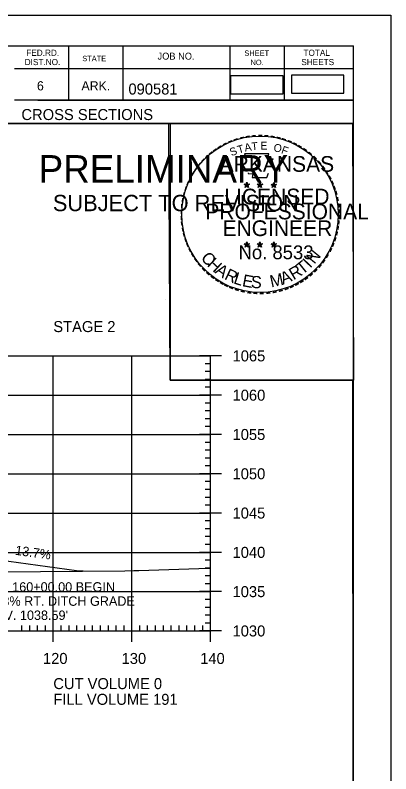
# Model space of a CAD drawing. Extents: x 1322838 to 1324533, y 339903 to 351025.
# Drawn here: x 1323818.9 to 1323866.6, y 345655.6 to 345752.1 of the extents above; entities that cross this region are included whole.
import ezdxf

# ---------------------------------------------------------------- set-up
doc = ezdxf.new("R2010")
doc.units = 0
for name, color, linetype in [('R_Axis', 7, 'Continuous'), ('R_Axis Annot', 7, 'Continuous'), ('R_Border', 7, 'Continuous'), ('R_Border PE', 7, 'Continuous'), ('R_Border Prem', 7, 'Continuous'), ('R_Drive', 7, 'Continuous'), ('R_Exist Surface', 7, 'Continuous'), ('R_Grid', 7, 'Continuous'), ('R_No Plot', 7, 'Continuous')]:
    doc.layers.add(name, color=color, linetype=linetype)

msp = doc.modelspace()

# ---------------------------------------------------------------- linework, layer by layer
at = {"layer": 'R_Axis'}
for p, q in [((1323845.115, 345708.745), (1323842.315, 345708.745)), ((1323843.715, 345673.745), (1323843.715, 345708.745)), ((1323843.715, 345707.745), (1323843.015, 345707.745)), ((1323843.715, 345706.745), (1323843.015, 345706.745)), ((1323843.715, 345705.745), (1323843.015, 345705.745)), ((1323843.715, 345704.745), (1323843.015, 345704.745)), ((1323845.115, 345703.745), (1323842.315, 345703.745)), ((1323843.715, 345702.745), (1323843.015, 345702.745)), ((1323843.715, 345701.745), (1323843.015, 345701.745)), ((1323843.715, 345700.745), (1323843.015, 345700.745)), ((1323843.715, 345699.745), (1323843.015, 345699.745)), ((1323845.115, 345698.745), (1323842.315, 345698.745)), ((1323843.715, 345697.745), (1323843.015, 345697.745)), ((1323843.715, 345696.745), (1323843.015, 345696.745)), ((1323843.715, 345695.745), (1323843.015, 345695.745)), ((1323843.715, 345694.745), (1323843.015, 345694.745)), ((1323845.115, 345693.745), (1323842.315, 345693.745)), ((1323843.715, 345692.745), (1323843.015, 345692.745)), ((1323843.715, 345691.745), (1323843.015, 345691.745)), ((1323843.715, 345690.745), (1323843.015, 345690.745)), ((1323843.715, 345689.745), (1323843.015, 345689.745)), ((1323845.115, 345688.745), (1323842.315, 345688.745)), ((1323843.715, 345687.745), (1323843.015, 345687.745)), ((1323843.715, 345686.745), (1323843.015, 345686.745)), ((1323843.715, 345685.745), (1323843.015, 345685.745)), ((1323843.715, 345684.745), (1323843.015, 345684.745)), ((1323845.115, 345683.745), (1323842.315, 345683.745)), ((1323843.715, 345682.745), (1323843.015, 345682.745)), ((1323843.715, 345681.745), (1323843.015, 345681.745)), ((1323843.715, 345680.745), (1323843.015, 345680.745)), ((1323843.715, 345679.745), (1323843.015, 345679.745)), ((1323845.115, 345678.745), (1323842.315, 345678.745)), ((1323843.715, 345677.745), (1323843.015, 345677.745)), ((1323843.715, 345676.745), (1323843.015, 345676.745)), ((1323843.715, 345675.745), (1323843.015, 345675.745)), ((1323819.715, 345673.745), (1323819.715, 345674.445)), ((1323820.715, 345673.745), (1323820.715, 345674.445)), ((1323821.715, 345673.745), (1323821.715, 345674.445)), ((1323822.715, 345673.745), (1323822.715, 345674.445)), ((1323823.715, 345672.345), (1323823.715, 345675.145)), ((1323824.715, 345673.745), (1323824.715, 345674.445)), ((1323825.715, 345673.745), (1323825.715, 345674.445)), ((1323826.715, 345673.745), (1323826.715, 345674.445)), ((1323827.715, 345673.745), (1323827.715, 345674.445)), ((1323828.715, 345673.745), (1323828.715, 345674.445)), ((1323829.715, 345673.745), (1323829.715, 345674.445)), ((1323830.715, 345673.745), (1323830.715, 345674.445)), ((1323831.715, 345673.745), (1323831.715, 345674.445)), ((1323832.715, 345673.745), (1323832.715, 345674.445)), ((1323833.715, 345672.345), (1323833.715, 345675.145)), ((1323834.715, 345673.745), (1323834.715, 345674.445)), ((1323835.715, 345673.745), (1323835.715, 345674.445)), ((1323836.715, 345673.745), (1323836.715, 345674.445)), ((1323837.715, 345673.745), (1323837.715, 345674.445)), ((1323838.715, 345673.745), (1323838.715, 345674.445)), ((1323839.715, 345673.745), (1323839.715, 345674.445)), ((1323840.715, 345673.745), (1323840.715, 345674.445)), ((1323841.715, 345673.745), (1323841.715, 345674.445)), ((1323842.715, 345673.745), (1323842.715, 345674.445)), ((1323843.715, 345674.745), (1323843.015, 345674.745)), ((1323843.715, 345672.345), (1323843.715, 345675.145)), ((1323563.715, 345673.745), (1323843.715, 345673.745)), ((1323845.115, 345673.745), (1323842.315, 345673.745))]:
    msp.add_line(p, q, dxfattribs=at)
at = {"layer": 'R_Border'}
for p, q in [((1323545.715, 345748.205), (1323861.895, 345748.205)), ((1323825.635, 345748.205), (1323825.635, 345741.265)), ((1323832.575, 345748.205), (1323832.575, 345741.265)), ((1323846.155, 345748.205), (1323846.155, 345741.265)), ((1323853.095, 345748.205), (1323853.095, 345741.265)), ((1323861.895, 345542.745), (1323861.895, 345748.205)), ((1323861.895, 345745.265), (1323818.795, 345745.265)), ((1323861.895, 345745.285), (1323861.895, 345745.285)), ((1323861.895, 345741.265), (1323818.795, 345741.265)), ((1323821.755, 345741.265), (1323861.895, 345741.265)), ((1323861.895, 345738.325), (1323799.255, 345738.325))]:
    msp.add_line(p, q, dxfattribs=at)
at = {"layer": 'R_Border PE'}
for p, q in [((1323847.98, 345730.58), (1323848.329, 345730.469)), ((1323847.98, 345730.58), (1323848.233, 345730.535)), ((1323847.98, 345730.58), (1323848.217, 345730.458)), ((1323848.113, 345730.172), (1323848.329, 345730.469)), ((1323848.113, 345730.172), (1323848.239, 345730.416)), ((1323848.329, 345730.834), (1323848.288, 345730.582)), ((1323848.329, 345730.469), (1323848.329, 345730.834)), ((1323848.329, 345730.834), (1323848.378, 345730.584)), ((1323848.676, 345730.58), (1323848.329, 345730.469)), ((1323848.542, 345730.172), (1323848.329, 345730.469)), ((1323848.676, 345730.58), (1323848.39, 345730.531)), ((1323848.542, 345730.172), (1323848.405, 345730.463)), ((1323848.676, 345730.58), (1323848.472, 345730.478)), ((1323849.65, 345730.58), (1323849.999, 345730.469)), ((1323849.65, 345730.58), (1323849.903, 345730.535)), ((1323849.65, 345730.58), (1323849.887, 345730.458)), ((1323849.783, 345730.172), (1323849.999, 345730.469)), ((1323849.783, 345730.172), (1323849.909, 345730.416)), ((1323849.999, 345730.834), (1323849.958, 345730.582)), ((1323849.999, 345730.469), (1323849.999, 345730.834)), ((1323849.999, 345730.834), (1323850.048, 345730.584)), ((1323850.346, 345730.58), (1323849.999, 345730.469)), ((1323850.212, 345730.172), (1323849.999, 345730.469)), ((1323850.346, 345730.58), (1323850.06, 345730.531)), ((1323850.212, 345730.172), (1323850.075, 345730.463)), ((1323850.346, 345730.58), (1323850.142, 345730.478)), ((1323851.414, 345730.568), (1323851.763, 345730.457)), ((1323851.414, 345730.568), (1323851.667, 345730.523)), ((1323851.414, 345730.568), (1323851.651, 345730.446)), ((1323851.547, 345730.16), (1323851.763, 345730.457)), ((1323851.547, 345730.16), (1323851.673, 345730.404)), ((1323851.763, 345730.822), (1323851.722, 345730.57)), ((1323851.763, 345730.457), (1323851.763, 345730.822)), ((1323851.763, 345730.822), (1323851.812, 345730.572)), ((1323852.11, 345730.568), (1323851.763, 345730.457)), ((1323851.976, 345730.16), (1323851.763, 345730.457)), ((1323852.11, 345730.568), (1323851.824, 345730.519)), ((1323851.976, 345730.16), (1323851.839, 345730.451)), ((1323852.11, 345730.568), (1323851.906, 345730.466)), ((1323848.113, 345730.172), (1323848.327, 345730.389)), ((1323848.542, 345730.172), (1323848.327, 345730.386)), ((1323849.783, 345730.172), (1323849.997, 345730.389)), ((1323850.212, 345730.172), (1323849.997, 345730.386)), ((1323851.547, 345730.16), (1323851.761, 345730.377)), ((1323851.976, 345730.16), (1323851.761, 345730.374)), ((1323847.976, 345723.007), (1323848.325, 345722.896)), ((1323847.976, 345723.007), (1323848.229, 345722.962)), ((1323847.976, 345723.007), (1323848.213, 345722.885)), ((1323848.109, 345722.599), (1323848.325, 345722.896)), ((1323848.109, 345722.599), (1323848.235, 345722.843)), ((1323848.109, 345722.599), (1323848.323, 345722.816)), ((1323848.325, 345723.261), (1323848.284, 345723.009)), ((1323848.538, 345722.599), (1323848.323, 345722.813)), ((1323848.325, 345722.896), (1323848.325, 345723.261)), ((1323848.325, 345723.261), (1323848.374, 345723.011)), ((1323848.672, 345723.007), (1323848.325, 345722.896)), ((1323848.538, 345722.599), (1323848.325, 345722.896)), ((1323848.672, 345723.007), (1323848.386, 345722.958)), ((1323848.538, 345722.599), (1323848.401, 345722.89)), ((1323848.672, 345723.007), (1323848.468, 345722.905)), ((1323849.645, 345723.007), (1323849.994, 345722.896)), ((1323849.645, 345723.007), (1323849.898, 345722.962)), ((1323849.645, 345723.007), (1323849.882, 345722.885)), ((1323849.778, 345722.599), (1323849.994, 345722.896)), ((1323849.778, 345722.599), (1323849.904, 345722.843)), ((1323849.778, 345722.599), (1323849.992, 345722.816)), ((1323849.994, 345723.261), (1323849.953, 345723.009)), ((1323850.207, 345722.599), (1323849.992, 345722.813)), ((1323849.994, 345722.896), (1323849.994, 345723.261)), ((1323849.994, 345723.261), (1323850.043, 345723.011)), ((1323850.341, 345723.007), (1323849.994, 345722.896)), ((1323850.207, 345722.599), (1323849.994, 345722.896)), ((1323850.341, 345723.007), (1323850.055, 345722.958)), ((1323850.207, 345722.599), (1323850.07, 345722.89)), ((1323850.341, 345723.007), (1323850.137, 345722.905)), ((1323851.412, 345722.997), (1323851.761, 345722.886)), ((1323851.412, 345722.997), (1323851.665, 345722.952)), ((1323851.412, 345722.997), (1323851.649, 345722.875)), ((1323851.545, 345722.589), (1323851.761, 345722.886)), ((1323851.545, 345722.589), (1323851.671, 345722.833)), ((1323851.545, 345722.589), (1323851.759, 345722.806)), ((1323851.761, 345723.251), (1323851.72, 345722.999)), ((1323851.974, 345722.589), (1323851.759, 345722.803)), ((1323851.761, 345722.886), (1323851.761, 345723.251)), ((1323851.761, 345723.251), (1323851.81, 345723.001)), ((1323852.108, 345722.997), (1323851.761, 345722.886)), ((1323851.974, 345722.589), (1323851.761, 345722.886)), ((1323852.108, 345722.997), (1323851.822, 345722.948)), ((1323851.974, 345722.589), (1323851.837, 345722.88)), ((1323852.108, 345722.997), (1323851.904, 345722.895))]:
    msp.add_line(p, q, dxfattribs=at)
for points in [[(1323848.021, 345734.458), (1323848.29, 345733.631)], [(1323851.532, 345733.536), (1323851.674, 345733.82), (1323850.989, 345733.796), (1323851.137, 345734.458), (1323848.021, 345734.458)], [(1323848.513, 345732.035), (1323848.513, 345731.948), (1323849.076, 345731.929), (1323849.022, 345731.456), (1323850.892, 345731.456), (1323851.093, 345731.992)], [(1323848.329, 345730.834), (1323848.542, 345730.172), (1323847.98, 345730.58), (1323848.676, 345730.58), (1323848.113, 345730.172), (1323848.329, 345730.834)], [(1323849.999, 345730.834), (1323850.212, 345730.172), (1323849.65, 345730.58), (1323850.346, 345730.58), (1323849.783, 345730.172), (1323849.999, 345730.834)], [(1323851.763, 345730.822), (1323851.976, 345730.16), (1323851.414, 345730.568), (1323852.11, 345730.568), (1323851.547, 345730.16), (1323851.763, 345730.822)], [(1323848.325, 345723.261), (1323848.538, 345722.599), (1323847.976, 345723.007), (1323848.672, 345723.007), (1323848.109, 345722.599), (1323848.325, 345723.261)], [(1323849.994, 345723.261), (1323850.207, 345722.599), (1323849.645, 345723.007), (1323850.341, 345723.007), (1323849.778, 345722.599), (1323849.994, 345723.261)], [(1323851.761, 345723.251), (1323851.974, 345722.589), (1323851.412, 345722.997), (1323852.108, 345722.997), (1323851.545, 345722.589), (1323851.761, 345723.251)]]:
    msp.add_lwpolyline(points, dxfattribs=at)
for centre, radius in [((1323848.328, 345730.468), 0.172), ((1323848.328, 345730.468), 0.145), ((1323848.328, 345730.468), 0.116), ((1323848.328, 345730.468), 0.0991), ((1323848.328, 345730.468), 0.0747), ((1323848.328, 345730.468), 0.0495), ((1323848.328, 345730.468), 0.0296), ((1323849.998, 345730.468), 0.172), ((1323849.998, 345730.468), 0.145), ((1323849.998, 345730.468), 0.116), ((1323849.998, 345730.468), 0.0991), ((1323849.998, 345730.468), 0.0747), ((1323849.998, 345730.468), 0.0495), ((1323849.998, 345730.468), 0.0296), ((1323851.762, 345730.456), 0.172), ((1323851.762, 345730.456), 0.145), ((1323851.762, 345730.456), 0.116), ((1323851.762, 345730.456), 0.0991), ((1323851.762, 345730.456), 0.0747), ((1323851.762, 345730.456), 0.0495), ((1323851.762, 345730.456), 0.0296), ((1323848.324, 345722.895), 0.172), ((1323848.324, 345722.895), 0.145), ((1323848.324, 345722.895), 0.116), ((1323848.324, 345722.895), 0.0991), ((1323848.324, 345722.895), 0.0747), ((1323848.324, 345722.895), 0.0495), ((1323848.324, 345722.895), 0.0296), ((1323849.993, 345722.895), 0.172), ((1323849.993, 345722.895), 0.145), ((1323849.993, 345722.895), 0.116), ((1323849.993, 345722.895), 0.0991), ((1323849.993, 345722.895), 0.0747), ((1323849.993, 345722.895), 0.0495), ((1323849.993, 345722.895), 0.0296), ((1323851.76, 345722.885), 0.172), ((1323851.76, 345722.885), 0.145), ((1323851.76, 345722.885), 0.116), ((1323851.76, 345722.885), 0.0991), ((1323851.76, 345722.885), 0.0747), ((1323851.76, 345722.885), 0.0495), ((1323851.76, 345722.885), 0.0296)]:
    msp.add_circle(centre, radius, dxfattribs=at)
at = {"layer": 'R_Drive'}
for points in [[(1323846.253, 345742.086), (1323852.936, 345742.086), (1323852.936, 345744.396), (1323846.253, 345744.396)], [(1323853.999, 345742.169), (1323860.682, 345742.169), (1323860.682, 345744.479), (1323853.999, 345744.479)]]:
    msp.add_lwpolyline(points, close=True, dxfattribs=at)
msp.add_lwpolyline([(1323816.765, 345682.812), (1323826.672, 345681.452), (1323827.51, 345681.376)], dxfattribs=at)
at = {"layer": 'R_Exist Surface'}
msp.add_lwpolyline([(1323756.655, 345682.54), (1323773.488, 345682.087), (1323778.68, 345681.951), (1323778.94, 345681.946), (1323797.876, 345681.308), (1323800.585, 345681.201), (1323801.066, 345680.706), (1323803.42, 345679.339), (1323806.691, 345679.435), (1323808.978, 345679.487), (1323810.939, 345680.269), (1323814.282, 345681.112), (1323816.671, 345681.266), (1323832.816, 345681.397), (1323833.957, 345681.419), (1323834.587, 345681.449), (1323843.511, 345681.724), (1323843.715, 345681.73)], dxfattribs=at)
at = {"layer": 'R_Grid'}
for p, q in [((1323563.715, 345708.745), (1323843.715, 345708.745)), ((1323823.715, 345673.745), (1323823.715, 345708.745)), ((1323833.715, 345673.745), (1323833.715, 345708.745)), ((1323843.715, 345673.745), (1323843.715, 345708.745)), ((1323563.715, 345703.745), (1323843.715, 345703.745)), ((1323563.715, 345698.745), (1323843.715, 345698.745)), ((1323563.715, 345693.745), (1323843.715, 345693.745)), ((1323563.715, 345688.745), (1323843.715, 345688.745)), ((1323563.715, 345683.745), (1323843.715, 345683.745)), ((1323563.715, 345678.745), (1323843.715, 345678.745)), ((1323563.715, 345673.745), (1323843.715, 345673.745))]:
    msp.add_line(p, q, dxfattribs=at)
at = {"layer": 'R_No Plot'}
for p, q in [((1323533.315, 345752.099), (1323866.648, 345752.099)), ((1323837.93, 345715.869), (1323837.93, 345715.869))]:
    msp.add_line(p, q, dxfattribs=at)
for points in [[(1323533.308, 345752.099), (1323866.648, 345752.099), (1323866.648, 345538.762), (1323533.308, 345538.762)], [(1323779.635, 345748.205), (1323799.255, 345748.205), (1323799.255, 345738.325), (1323815.368, 345738.325), (1323838.567, 345738.325), (1323838.567, 345705.654), (1323861.775, 345705.654), (1323861.895, 345542.745), (1323545.715, 345542.745), (1323545.715, 345748.205)], [(1323838.427, 345738.325), (1323861.775, 345738.325), (1323861.915, 345705.654), (1323838.567, 345705.654)]]:
    msp.add_lwpolyline(points, close=True, dxfattribs=at)
msp.add_circle((1323850.007, 345726.765), 9.952, dxfattribs=at)

# ---------------------------------------------------------------- texts
at = {"layer": 'R_Axis Annot'}
for s, p in [('STAGE 2', (1323823.715, 345711.775)), ('1065', (1323846.515, 345708.045)), ('1060', (1323846.515, 345703.045)), ('1055', (1323846.515, 345698.045)), ('1050', (1323846.515, 345693.045)), ('1045', (1323846.515, 345688.045)), ('1040', (1323846.515, 345683.045)), ('1035', (1323846.515, 345678.045)), ('1030', (1323846.515, 345673.045)), ('120', (1323822.398, 345669.545)), ('130', (1323832.398, 345669.545)), ('140', (1323842.398, 345669.545)), ('CUT VOLUME 0', (1323823.715, 345666.345)), ('FILL VOLUME 191', (1323823.715, 345664.345))]:
    msp.add_text(s, height=1.4, dxfattribs=at).set_placement(p)
at = {"layer": 'R_Border'}
for s, height, p in [('FED.RD.', 0.7819, (1323820.275, 345746.925)), ('STATE', 0.684, (1323827.395, 345746.245)), ('JOB NO.', 0.8792, (1323836.975, 345746.445)), ('SHEET', 0.684, (1323848.015, 345746.925)), ('TOTAL', 0.7819, (1323855.535, 345746.925)), ('DIST.NO.', 0.7819, (1323820.075, 345745.745)), ('NO.', 0.684, (1323848.795, 345745.745)), ('SHEETS', 0.7819, (1323855.255, 345745.745)), ('6', 1.172, (1323821.635, 345742.525)), ('ARK.', 1.1723, (1323827.295, 345742.525)), ('090581', 1.4, (1323833.271, 345742.004)), ('CROSS SECTIONS', 1.4, (1323819.659, 345738.755))]:
    msp.add_text(s, height=height, rotation=360, dxfattribs=at).set_placement(p)
at = {"layer": 'R_Border PE'}
for s, height, rotation, p in [('-', 1.6, 24.30721, (1323846.135, 345735.316)), ('-', 1.6, 19.17608, (1323846.769, 345735.585)), ('-', 1.6, 13.63015, (1323847.519, 345735.826)), ('-', 1.6, 10.21935, (1323848.197, 345735.988)), ('-', 1.6, 5.89682, (1323848.926, 345736.098)), ('-', 1.6, 0.18623, (1323849.698, 345736.17)), ('-', 1.6, 357.74304, (1323850.421, 345736.157)), ('-', 1.6, 352.16172, (1323851.165, 345736.101)), ('-', 1.6, 347.20489, (1323851.884, 345735.987)), ('-', 1.6, 342.3362, (1323852.519, 345735.832)), ('-', 1.6, 337.85509, (1323853.254, 345735.609)), ('-', 1.6, 34.06357, (1323844.905, 345734.629)), ('-', 1.6, 28.79182, (1323845.502, 345734.999)), ('S', 1, 21.59401, (1323846.376, 345734.136)), ('T', 1, 16.4036, (1323847.29, 345734.467)), ('A', 1, 11.21318, (1323848.116, 345734.718)), ('T', 1, 6.02276, (1323848.965, 345734.884)), ('E', 1, 0.83234, (1323850.07, 345734.994)), ('O', 1, 350.4515, (1323851.674, 345734.784)), ('F', 1, 340.07066, (1323852.628, 345734.556)), ('-', 1.6, 334.12109, (1323853.885, 345735.338)), ('-', 1.6, 329.64089, (1323854.464, 345735.055)), ('-', 1.6, 42.96224, (1323843.418, 345733.439)), ('-', 1.6, 38.95066, (1323843.851, 345733.856)), ('-', 1.6, 36.23174, (1323844.327, 345734.234)), ('-', 1.6, 325.86266, (1323855.107, 345734.694)), ('-', 1.6, 320.52971, (1323855.717, 345734.268)), ('-', 1.6, 50.61417, (1323842.567, 345732.475)), ('-', 1.6, 48.42305, (1323842.97, 345732.961)), ('ARKANSAS', 2, 360, (1323844.874, 345732.17)), ('-', 1.6, 315.57859, (1323856.316, 345733.78)), ('-', 1.6, 309.87973, (1323856.885, 345733.23)), ('-', 1.6, 54.23247, (1323842.154, 345731.908)), ('-', 1.6, 306.65218, (1323857.41, 345732.628)), ('-', 1.4, 303.67529, (1323857.896, 345732.06)), ('-', 1.6, 62.87135, (1323841.516, 345730.767)), ('-', 1.6, 58.07063, (1323841.829, 345731.381)), ('-', 1.6, 299.66835, (1323858.215, 345731.453)), ('-', 1.6, 67.77427, (1323841.257, 345730.156)), ('DWB', 0.01, 360, (1323848.316, 345730.464)), ('DWB', 0.01, 360, (1323849.986, 345730.464)), ('DWB', 0.01, 360, (1323851.75, 345730.453)), ('-', 1.6, 294.66279, (1323858.539, 345730.841)), ('-', 1.6, 290.57283, (1323858.796, 345730.264)), ('-', 1.6, 75.46096, (1323840.841, 345728.812)), ('-', 1.6, 72.39447, (1323841.038, 345729.526)), ('LICENSED', 2, 360, (1323845.472, 345728.021)), ('-', 1.6, 285.12326, (1323859.03, 345729.684)), ('-', 1.6, 81.20126, (1323840.709, 345728.099)), ('-', 1.6, 280.54934, (1323859.23, 345728.942)), ('-', 1.6, 85.18634, (1323840.633, 345727.408)), ('PROFESSIONAL', 2, 360, (1323843.048, 345726.117)), ('-', 1.6, 276.59616, (1323859.392, 345728.174)), ('-', 1.6, 94.19588, (1323840.643, 345725.982)), ('-', 1.6, 89.06224, (1323840.608, 345726.707)), ('-', 1.6, 274.33011, (1323859.452, 345727.452)), ('-', 1.6, 269.94067, (1323859.486, 345726.82)), ('-', 1.6, 98.94793, (1323840.715, 345725.315)), ('ENGINEER', 2, 360, (1323845.235, 345723.992)), ('-', 1.6, 263.5172, (1323859.467, 345726.154)), ('-', 1.6, 101.71495, (1323840.85, 345724.582)), ('-', 1.6, 260.99529, (1323859.396, 345725.5)), ('-', 1.6, 105.45785, (1323841.012, 345723.987)), ('-', 1.6, 109.08742, (1323841.227, 345723.356)), ('-', 1.6, 252.86809, (1323859.105, 345724.102)), ('-', 1.6, 255.7626, (1323859.286, 345724.822)), ('-', 1.6, 114.06432, (1323841.481, 345722.76)), ('No. 8533', 1.757, 360, (1323847.278, 345721.041)), ('DWB', 0.01, 360, (1323848.312, 345722.891)), ('DWB', 0.01, 360, (1323849.981, 345722.891)), ('DWB', 0.01, 360, (1323851.748, 345722.881)), ('-', 1.6, 247.88866, (1323858.882, 345723.429)), ('-', 1.6, 115.72885, (1323841.786, 345722.142)), ('-', 1.6, 120.44712, (1323842.143, 345721.556)), ('C', 1.54, 309.95483, (1323842.4, 345721.188)), ('N', 1.54, 50.78344, (1323856.914, 345720.34)), ('-', 1.6, 244.61971, (1323858.62, 345722.8)), ('-', 1.6, 125.89344, (1323842.546, 345720.995)), ('H', 1.54, 317.38726, (1323843.185, 345720.25)), ('T', 1.54, 38.42805, (1323855.38, 345719.011)), ('I', 1.54, 46.30332, (1323856.392, 345719.82)), ('-', 1.6, 233.84524, (1323857.824, 345721.395)), ('-', 1.6, 239.07125, (1323858.226, 345722.048)), ('-', 1.6, 130.71812, (1323843.008, 345720.443)), ('-', 1.6, 134.22381, (1323843.525, 345719.898)), ('A', 1.54, 325.55777, (1323844.18, 345719.347)), ('R', 1.54, 334.31873, (1323845.378, 345718.546)), ('R', 1.54, 30.55277, (1323854.267, 345718.348)), ('-', 1.6, 225.76533, (1323856.915, 345720.265)), ('-', 1.6, 231.25377, (1323857.394, 345720.829)), ('-', 1.6, 138.93382, (1323844.05, 345719.434)), ('-', 1.6, 144.64634, (1323844.606, 345719.028)), ('L', 1.54, 342.19401, (1323846.548, 345717.989)), ('E', 1.54, 349.33121, (1323847.665, 345717.627)), ('S', 1.54, 356.46841, (1323848.818, 345717.407)), ('M', 1.54, 12.44038, (1323851.439, 345717.441)), ('A', 1.54, 21.7918, (1323852.935, 345717.797)), ('-', 1.6, 221.08509, (1323856.393, 345719.756)), ('-', 1.6, 148.08978, (1323845.167, 345718.657)), ('-', 1.6, 151.57039, (1323845.746, 345718.332)), ('-', 1.6, 154.60019, (1323846.268, 345718.085)), ('-', 1.6, 207.35684, (1323854.752, 345718.551)), ('-', 1.6, 212.24909, (1323855.31, 345718.897)), ('-', 1.6, 215.73633, (1323855.844, 345719.284)), ('-', 1.6, 158.56121, (1323846.892, 345717.831)), ('-', 1.6, 162.79826, (1323847.579, 345717.618)), ('-', 1.6, 167.55551, (1323848.294, 345717.454)), ('-', 1.6, 173.11546, (1323849.066, 345717.344)), ('-', 1.6, 191.28576, (1323852.103, 345717.518)), ('-', 1.6, 195.47429, (1323852.832, 345717.717)), ('-', 1.6, 200.71842, (1323853.509, 345717.959)), ('-', 1.6, 204.25161, (1323854.128, 345718.232)), ('-', 1.6, 176.51827, (1323849.814, 345717.291)), ('-', 1.6, 181.59176, (1323850.558, 345717.31)), ('-', 1.6, 185.81666, (1323851.367, 345717.386))]:
    msp.add_text(s, height=height, rotation=rotation, dxfattribs=at).set_placement(p)
at = {"layer": 'R_Border Prem'}
for s, height, p in [('PRELIMINARY', 3.5, (1323821.847, 345730.788)), ('DWB', 0.01, (1323822.593, 345732.637)), ('SUBJECT TO REVISION', 2.07511, (1323823.656, 345727.159))]:
    msp.add_text(s, height=height, rotation=360, dxfattribs=at).set_placement(p)
at = {"layer": 'R_Drive'}
msp.add_text('13.7%', height=1.2, rotation=352.18289, dxfattribs=at).set_placement((1323818.811, 345683.444))
for s, p in [('STA. 160+00.00 BEGIN', (1323814.474, 345678.745)), ('-5.83% RT. DITCH GRADE', (1323814.474, 345676.945)), ("ELEV. 1038.59'", (1323814.474, 345675.145))]:
    msp.add_text(s, height=1.2, dxfattribs=at).set_placement(p)

doc.saveas('drawing.dxf')
